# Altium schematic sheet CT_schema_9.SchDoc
size 402 x 220 mm
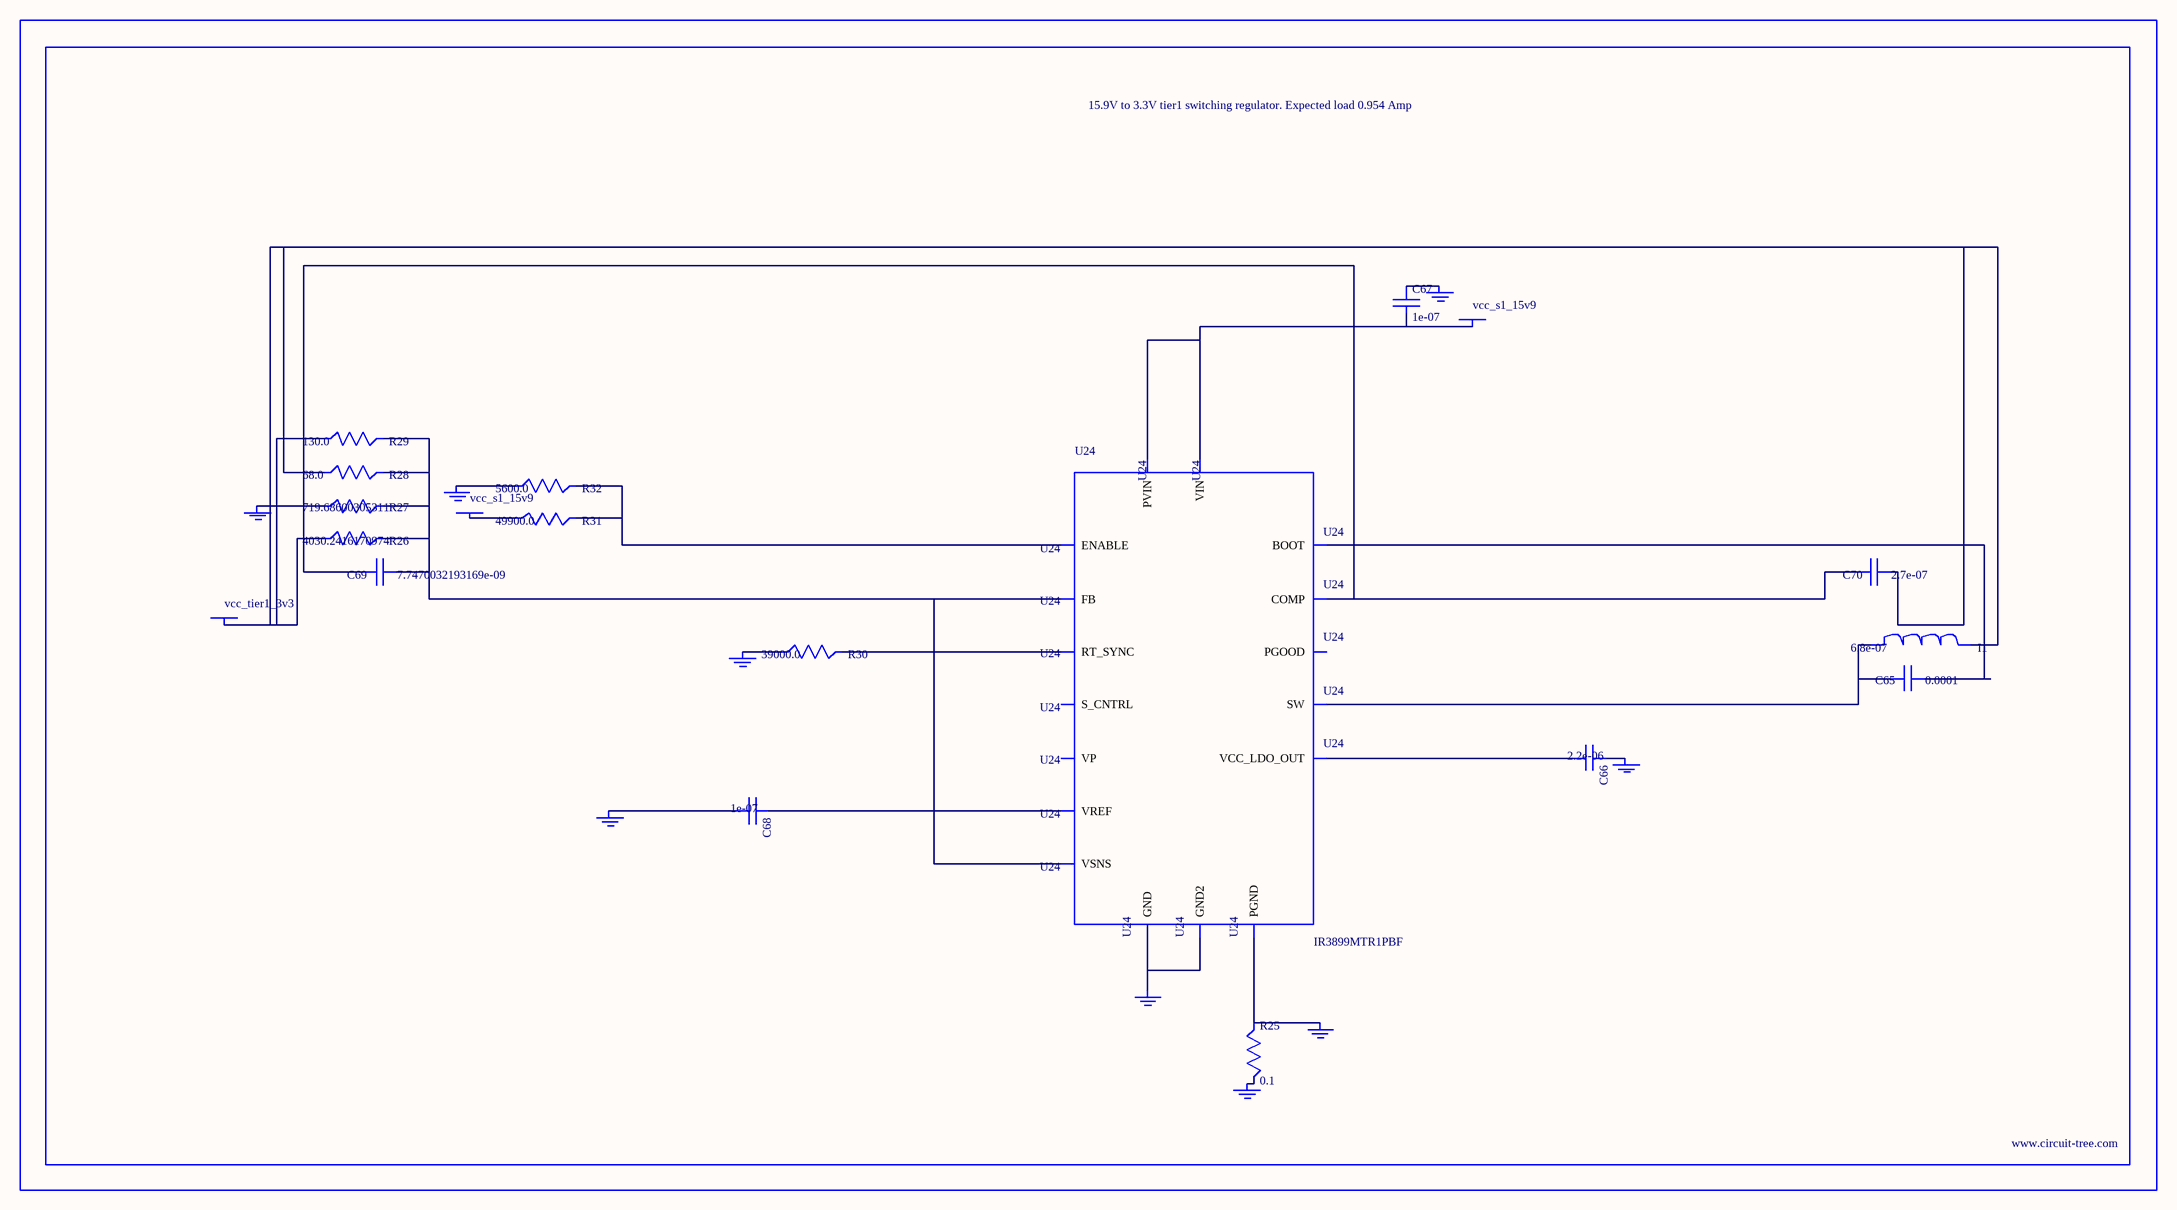
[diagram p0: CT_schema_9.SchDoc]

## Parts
BORDER8  (no value)
C65  0.0001  [C1210]
C66  2.2e-06  [C0603]
C67  1e-07  [C0402]
C68  1e-07  [C0402]
C69  7.7470032193169e-09  [R0603]
C70  2.7e-07  [C0603]
GND_INSTANCE_8_0  (no value)
GND_INSTANCE_8_1  (no value)
GND_INSTANCE_8_2  (no value)
GND_INSTANCE_8_3  (no value)
GND_INSTANCE_8_4  (no value)
GND_INSTANCE_8_5  (no value)
GND_INSTANCE_8_6  (no value)
GND_INSTANCE_8_7  (no value)
GND_INSTANCE_8_8  (no value)
I1  6.8e-07  [IND25X25CZ]
POWER_INSTANCE_8_0  vcc_s1_15v9
POWER_INSTANCE_8_1  vcc_s1_15v9
POWER_INSTANCE_8_2  vcc_tier1_3v3
R25  0.1  [R0603]
R26  4030.2416170974  [R0603]
R27  719.68600305311  [R0603]
R28  68.0  [R0603]
R29  130.0  [R0603]
R30  39000.0  [R0603]
R31  49900.0  [R0603]
R32  5600.0  [R0603]
U24  IR3899MTR1PBF  [IR3899MTR1PBF]

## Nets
NetC65_1: C65.1 U24.14(BOOT)
NetC65_2: C65.2 I1.1 U24.12(SW)
NetC66_1: C66.1 GND_INSTANCE_8_4.0(GND)
NetC66_2: C66.2 U24.10(VCC_LDO_OUT)
NetC67_1: C67.1 GND_INSTANCE_8_3.0(GND)
NetC67_2: C67.2 POWER_INSTANCE_8_0.0(PWR) U24.9(VIN) U24.13(PVIN)
NetC68_1: C68.1 U24.2(VREF)
NetC68_2: C68.2 GND_INSTANCE_8_1.0(GND)
NetC69_1: C69.1 R26.2 R27.2 R28.2 R29.2 U24.1(FB) U24.8(VSNS)
NetC69_2: C69.2 C70.2 U24.3(COMP)
NetC70_1: C70.1 I1.2 POWER_INSTANCE_8_2.0(PWR) R26.1 R28.1 R29.1
NetGND_INSTANCE_8_0_0: GND_INSTANCE_8_0.0(GND) R27.1
NetGND_INSTANCE_8_2_0: GND_INSTANCE_8_2.0(GND) R30.1
NetGND_INSTANCE_8_5_0: GND_INSTANCE_8_5.0(GND) R25.2
NetGND_INSTANCE_8_6_0: GND_INSTANCE_8_6.0(GND) R25.1 U24.11(PGND)
NetGND_INSTANCE_8_7_0: GND_INSTANCE_8_7.0(GND) R32.1
NetGND_INSTANCE_8_8_0: GND_INSTANCE_8_8.0(GND) U24.4(GND) U24.17(GND2)
NetPOWER_INSTANCE_8_1_0: POWER_INSTANCE_8_1.0(PWR) R31.1
NetR30_2: R30.2 U24.5(RT_SYNC)
NetR31_2: R31.2 R32.2 U24.15(ENABLE)

Not connected (* = marked no-connect by the designer): U24 6(S_CNTRL) 7(PGOOD) 16(VP)

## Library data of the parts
BORDER8 = BORDER_PAGE8
C65 = GRM32ER61A107ME20L
C66 = C0603C225K8RACTU
C67 C68 = C0402C104K3RACTU
C69 = C69
C70 = C0603C274K3RAC
GND_INSTANCE_8_0-GND_INSTANCE_8_8 = GND
I1 = IHLP2525CZERR68M01
POWER_INSTANCE_8_0-POWER_INSTANCE_8_2 = PWR
R25 = ERJ-3RSFR10V
R26 = R26
R27 = R27
R28 = RC0603JR-0768RL
R29 = RC0603JR-07130RL
R30 = RC0603JR-0739KL
R31 = RC0603FR-0749K9
R32 = RC0603JR-075K6L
